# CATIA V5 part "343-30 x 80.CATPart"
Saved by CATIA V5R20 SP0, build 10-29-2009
Part number: 343-30 x 80
Definition: NONE
Nomenclature: 343-30 x 80
Source: Unknown
Description: 343-30 x 80
Bounding box of the stored display mesh (mm): x 0 to 80, y -22.5 to 22.5, z -22.5 to 22.5
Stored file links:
  C:\Users\Utente\Desktop\IO LAVORO\3D X SITO CF\X SITO\343-348\343-30 x 80.CATPart
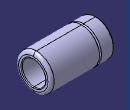
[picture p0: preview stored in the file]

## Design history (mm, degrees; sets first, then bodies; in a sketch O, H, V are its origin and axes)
Body1 "343-30 x 80" (main body)
  Solid1: solid without history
